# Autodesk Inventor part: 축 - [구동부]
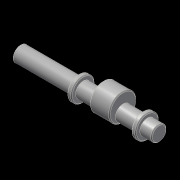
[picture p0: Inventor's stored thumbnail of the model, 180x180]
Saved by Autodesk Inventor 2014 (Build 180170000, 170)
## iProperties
Company: 한국ATC센터
Created: 2014-08
Part Number: 축 - [구동부]
Document SubType Name: Modeling
Designer: KYOUNG IL JANG
Density: 7.86 g/cm^3
Material: 강, 연강
Appearance: 강철
Mass: 375.441 g
Surface Area: 117.379 cm^2
Volume: 47.766 cm^3
Author: KYOUNG IL JANG
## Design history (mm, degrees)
sketch "스케치1"
  geometry: L1 (-76.5, 0)-(76.5, 0); L2 (-76.5, 0)-(-76.5, 8.5); L3 (-76.5, 8.5)-(-12.5, 8.5); L4 (-12.5, 8.5)-(-12.5, 13); L5 (-12.5, 13)-(-7.5, 13); L6 (-7.5, 13)-(-7.5, 8.5); L7 (-7.5, 8.5)-(58.5, 8.5); L8 (58.5, 8.5)-(58.5, 13); L9 (58.5, 13)-(63.5, 13); L10 (63.5, 13)-(63.5, 8.5); L11 (63.5, 8.5)-(76.5, 8.5); L12 (76.5, 8.5)-(76.5, 0); 2 further points
  constraints: 24 end point, 5 parallel, 1 coincident, 1 horizontal, 1 midpoint, 1 perpendicular
  dimensions: "d0" = 153 distance of L1.start L1.end (derived); "d2" = 17 diameter of L3 L1; "d3" = 26 diameter of L5 L1; "d4" = 17 diameter of L7 L1; "d5" = 26 diameter of L9 L1; "d6" = 17 diameter of L11 L1; "d7" = 5 distance of L8.end L9.end; "d8" = 5 distance of L4.end L5.end; "d10" = 64 distance of L2.end L3.end; "d11" = 13 distance of L10.end L11.end; "d35" = 66 distance between parallel lines of L8 L6
revolve "회전1" sketch "스케치1" stored, may be unused: angle "d12" = 90 deg
node "작업 평면1"
node "작업 평면2"
node "작업 평면4"
sketch "스케치6"
  geometry: C1 r 15 at (-5, -6); 1 further point
  constraints: 1 centre point, 1 horizontal alignment
  dimensions: "d31" = 30 diameter of C1; "d32" = 5 distance of C1.centre point (0, -6)
extrude "돌출4" join sketch "스케치6" stored distance "d33" = 22; taper "d34" = 0 deg
node "작업 평면3"
sketch "스케치5"
  geometry: L1 (32, 8.5)-(32, -8.5) reference; L2 (32, -2.5)-(14.5, -2.5); L3 (14.5, 2.5)-(32, 2.5); A1 r 2.5 centre (14.5, 0) between (14.5, 2.5) and (14.5, -2.5); 2 further points
  constraints: 4 end point, 2 point on circle, 2 point on line, 2 tangent, 1 centre point, 1 midpoint, 1 parallel, 1 perpendicular
  dimensions: "d23" = 5 distance between parallel lines of L3 L2; "d36" = 20 dimension on A1 L1
extrude "돌출3" cut sketch "스케치5" distance "d25" = 3; taper "d26" = 0 deg
chamfer "모따기1" distance "d27" = 1; stored, may be unused: second distance "d28" = 2, angle "d29" = 45 deg
node "솔리드1"
other parameters: "d13" = 9.5, "d18" = 9.5
